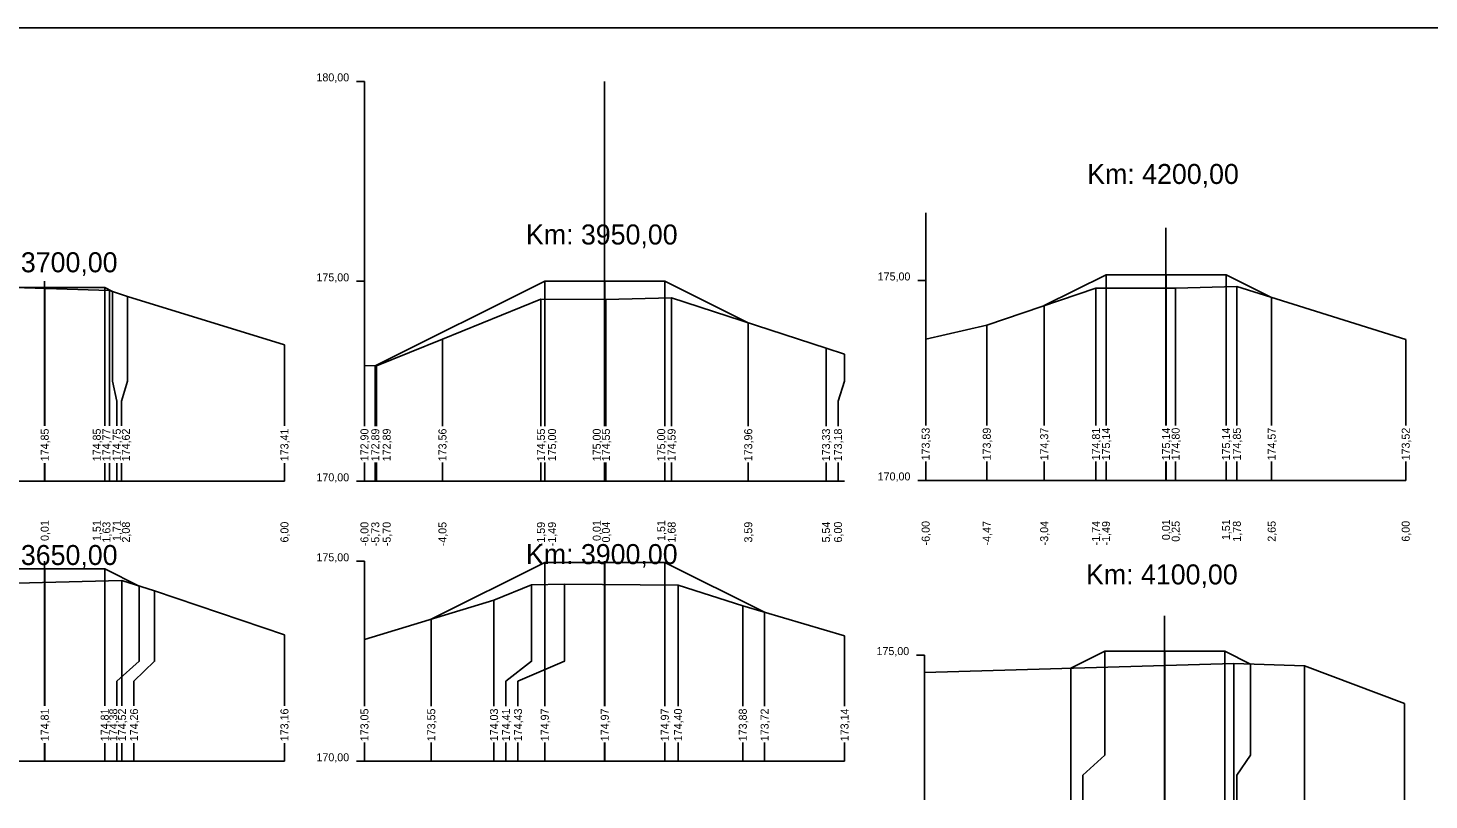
# Model space of a CAD drawing. Extents: x -614174 to -599765, y -1185887 to -1181080.
# Drawn here: x -601012.8 to -600977.78, y -1184510.24 to -1184490.94 of the extents above; entities that cross this region are included whole.
import ezdxf

# ---------------------------------------------------------------- set-up
doc = ezdxf.new("R2010")
doc.units = 0
for name, color, linetype in [('11', 7, 'Continuous'), ('16', 7, 'Continuous'), ('21', 7, 'Continuous'), ('28', 7, 'Continuous'), ('59', 7, 'Continuous'), ('8', 7, 'Continuous'), ('návrh', 7, 'Continuous')]:
    doc.layers.add(name, color=color, linetype=linetype)

msp = doc.modelspace()

# ---------------------------------------------------------------- linework, layer by layer
for points in [[(-600987.397, -1184497.877), (-600985.852, -1184497.104), (-600984.352, -1184497.104), (-600982.852, -1184497.104), (-600981.711, -1184497.675)], [(-600985.852, -1184497.104), (-600985.852, -1184497.104), (-600985.852, -1184497.104)], [(-600984.352, -1184497.104), (-600984.352, -1184497.104), (-600984.352, -1184497.104)], [(-600982.852, -1184497.104), (-600982.852, -1184497.104), (-600982.852, -1184497.104)], [(-601018.389, -1184498.698), (-601014.223, -1184497.525), (-601013.935, -1184497.41), (-601013.687, -1184497.404), (-601010.762, -1184497.497), (-601010.312, -1184497.649), (-601006.389, -1184498.857)], [(-601013.972, -1184497.424), (-601013.881, -1184497.424), (-601012.381, -1184497.424), (-601010.881, -1184497.424), (-601010.683, -1184497.524)], [(-601012.381, -1184497.424), (-601012.381, -1184497.424), (-601012.381, -1184497.424)], [(-601010.881, -1184497.424), (-601010.881, -1184497.424), (-601010.881, -1184497.424)], [(-601004.118, -1184499.383), (-600999.881, -1184497.265), (-600998.381, -1184497.265), (-600996.881, -1184497.265), (-600994.795, -1184498.308)], [(-600999.881, -1184497.265), (-600999.881, -1184497.265), (-600999.881, -1184497.265)], [(-600998.381, -1184497.265), (-600998.381, -1184497.265), (-600998.381, -1184497.265)], [(-600996.881, -1184497.265), (-600996.881, -1184497.265), (-600996.881, -1184497.265)], [(-600990.36, -1184498.72), (-600988.832, -1184498.362), (-600986.104, -1184497.439), (-600984.111, -1184497.444), (-600982.581, -1184497.403), (-600978.36, -1184498.724)], [(-601004.389, -1184499.372), (-601004.091, -1184499.384), (-601002.439, -1184498.714), (-600999.977, -1184497.716), (-600998.353, -1184497.722), (-600996.711, -1184497.682), (-600992.851, -1184498.944), (-600992.389, -1184499.092)], [(-600987.397, -1184497.877), (-600987.397, -1184497.877), (-600987.396, -1184497.877)], [(-601004.118, -1184499.383), (-601004.118, -1184499.383), (-601004.117, -1184499.383)], [(-601015.736, -1184505.384), (-601013.881, -1184504.456), (-601012.381, -1184504.456), (-601010.881, -1184504.456), (-601010.018, -1184504.888)], [(-601012.381, -1184504.456), (-601012.381, -1184504.456), (-601012.381, -1184504.456)], [(-601010.881, -1184504.456), (-601010.881, -1184504.456), (-601010.881, -1184504.456)], [(-601002.719, -1184505.716), (-600999.881, -1184504.297), (-600998.381, -1184504.297), (-600996.881, -1184504.297), (-600994.386, -1184505.545)], [(-600999.881, -1184504.297), (-600999.881, -1184504.297), (-600999.881, -1184504.297)], [(-600998.381, -1184504.297), (-600998.381, -1184504.297), (-600998.381, -1184504.297)], [(-600996.881, -1184504.297), (-600996.881, -1184504.297), (-600996.881, -1184504.297)], [(-601018.389, -1184506.455), (-601014.885, -1184505.04), (-601014.252, -1184504.822), (-601013.765, -1184504.83), (-601010.45, -1184504.75), (-601009.636, -1184505.01), (-601006.389, -1184506.105)], [(-601004.389, -1184506.223), (-601001.151, -1184505.24), (-601000.213, -1184504.862), (-600999.391, -1184504.843), (-600996.55, -1184504.871), (-600994.931, -1184505.385), (-600992.389, -1184506.131)], [(-601002.718, -1184505.715), (-601002.719, -1184505.716), (-601002.719, -1184505.716)], [(-600986.729, -1184506.945), (-600985.881, -1184506.521), (-600984.381, -1184506.521), (-600982.881, -1184506.521), (-600982.24, -1184506.842)], [(-600985.881, -1184506.521), (-600985.881, -1184506.521), (-600985.881, -1184506.521)], [(-600984.381, -1184506.521), (-600984.381, -1184506.521), (-600984.381, -1184506.521)], [(-600982.881, -1184506.521), (-600982.881, -1184506.521), (-600982.881, -1184506.521)], [(-600990.389, -1184507.05), (-600982.655, -1184506.828), (-600980.894, -1184506.885), (-600978.389, -1184507.822)], [(-600986.729, -1184506.945), (-600986.729, -1184506.945), (-600986.729, -1184506.945)]]:
    msp.add_lwpolyline(points)
at = {"layer": '11'}
for points in [[(-600985.852, -1184497.104), (-600985.852, -1184499.748), (-600985.852, -1184500.248), (-600985.852, -1184500.871)], [(-600984.352, -1184497.104), (-600984.352, -1184499.748), (-600984.352, -1184500.248), (-600984.352, -1184500.871)], [(-600982.852, -1184497.104), (-600982.852, -1184499.748), (-600982.852, -1184500.248), (-600982.852, -1184500.871)], [(-601012.381, -1184497.424), (-601012.381, -1184499.77), (-601012.381, -1184500.27), (-601012.381, -1184500.884)], [(-601010.881, -1184497.424), (-601010.881, -1184499.77), (-601010.881, -1184500.27), (-601010.881, -1184500.884)], [(-601010.762, -1184497.497), (-601010.762, -1184499.77), (-601010.762, -1184500.27), (-601010.762, -1184500.884)], [(-601010.683, -1184497.524), (-601010.683, -1184499.77), (-601010.581, -1184500.27), (-601010.581, -1184500.884)], [(-600999.881, -1184497.265), (-600999.881, -1184499.77), (-600999.881, -1184500.27), (-600999.881, -1184500.892)], [(-600998.381, -1184497.265), (-600998.381, -1184499.77), (-600998.381, -1184500.27), (-600998.381, -1184500.892)], [(-600996.881, -1184497.265), (-600996.881, -1184499.77), (-600996.881, -1184500.27), (-600996.881, -1184500.892)], [(-600986.104, -1184497.439), (-600986.104, -1184499.748), (-600986.104, -1184500.248), (-600986.104, -1184500.871)], [(-600984.111, -1184497.444), (-600984.111, -1184499.748), (-600984.111, -1184500.248), (-600984.111, -1184500.871)], [(-600982.581, -1184497.403), (-600982.581, -1184499.748), (-600982.581, -1184500.248), (-600982.581, -1184500.871)], [(-601010.312, -1184497.649), (-601010.312, -1184499.77), (-601010.462, -1184500.27), (-601010.462, -1184500.884)], [(-600999.977, -1184497.716), (-600999.977, -1184499.77), (-600999.977, -1184500.27), (-600999.977, -1184500.892)], [(-600998.353, -1184497.722), (-600998.353, -1184499.77), (-600998.353, -1184500.27), (-600998.353, -1184500.892)], [(-600996.711, -1184497.682), (-600996.711, -1184499.77), (-600996.711, -1184500.27), (-600996.711, -1184500.892)], [(-600987.397, -1184497.877), (-600987.397, -1184499.748), (-600987.397, -1184500.248), (-600987.397, -1184500.871)], [(-600981.711, -1184497.675), (-600981.711, -1184499.748), (-600981.711, -1184500.248), (-600981.711, -1184500.871)], [(-600994.795, -1184498.308), (-600994.795, -1184499.77), (-600994.795, -1184500.27), (-600994.795, -1184500.892)], [(-600988.832, -1184498.362), (-600988.832, -1184499.748), (-600988.832, -1184500.248), (-600988.832, -1184500.871)], [(-601006.389, -1184498.857), (-601006.389, -1184499.77), (-601006.389, -1184500.27), (-601006.389, -1184500.884)], [(-601002.439, -1184498.714), (-601002.439, -1184499.77), (-601002.439, -1184500.27), (-601002.439, -1184500.892)], [(-600992.851, -1184498.944), (-600992.851, -1184499.77), (-600992.851, -1184500.27), (-600992.851, -1184500.892)], [(-600990.36, -1184498.72), (-600990.36, -1184499.748), (-600990.36, -1184500.248), (-600990.36, -1184500.871)], [(-600978.36, -1184498.724), (-600978.36, -1184499.748), (-600978.36, -1184500.248), (-600978.36, -1184500.871)], [(-600992.389, -1184499.092), (-600992.389, -1184499.77), (-600992.551, -1184500.27), (-600992.551, -1184500.892)], [(-601004.389, -1184499.372), (-601004.389, -1184499.77), (-601004.389, -1184500.27), (-601004.389, -1184500.892)], [(-601004.118, -1184499.383), (-601004.118, -1184499.77), (-601004.118, -1184500.27), (-601004.118, -1184500.892)], [(-601004.091, -1184499.384), (-601004.091, -1184499.77), (-601004.089, -1184500.27), (-601004.089, -1184500.892)], [(-601012.381, -1184501.82), (-601012.381, -1184502.27)], [(-601010.881, -1184501.82), (-601010.881, -1184502.27)], [(-601010.762, -1184501.82), (-601010.762, -1184502.27)], [(-601010.581, -1184501.82), (-601010.581, -1184502.27)], [(-601010.462, -1184501.82), (-601010.462, -1184502.27)], [(-601006.389, -1184501.82), (-601006.389, -1184502.27)], [(-601004.389, -1184501.8), (-601004.389, -1184502.27)], [(-601004.118, -1184501.8), (-601004.118, -1184502.27)], [(-601004.089, -1184501.8), (-601004.089, -1184502.27)], [(-601002.439, -1184501.8), (-601002.439, -1184502.27)], [(-600999.977, -1184501.8), (-600999.977, -1184502.27)], [(-600999.881, -1184501.8), (-600999.881, -1184502.27)], [(-600998.381, -1184501.8), (-600998.381, -1184502.27)], [(-600998.353, -1184501.8), (-600998.353, -1184502.27)], [(-600996.881, -1184501.8), (-600996.881, -1184502.27)], [(-600996.711, -1184501.8), (-600996.711, -1184502.27)], [(-600994.795, -1184501.8), (-600994.795, -1184502.27)], [(-600992.851, -1184501.8), (-600992.851, -1184502.27)], [(-600992.551, -1184501.8), (-600992.551, -1184502.27)], [(-600990.36, -1184501.779), (-600990.36, -1184502.248)], [(-600988.832, -1184501.779), (-600988.832, -1184502.248)], [(-600987.397, -1184501.779), (-600987.397, -1184502.248)], [(-600986.104, -1184501.779), (-600986.104, -1184502.248)], [(-600985.852, -1184501.779), (-600985.852, -1184502.248)], [(-600984.352, -1184501.779), (-600984.352, -1184502.248)], [(-600984.111, -1184501.779), (-600984.111, -1184502.248)], [(-600982.852, -1184501.779), (-600982.852, -1184502.248)], [(-600982.581, -1184501.779), (-600982.581, -1184502.248)], [(-600981.711, -1184501.779), (-600981.711, -1184502.248)], [(-600978.36, -1184501.779), (-600978.36, -1184502.248)], [(-601012.381, -1184504.456), (-601012.381, -1184506.77), (-601012.381, -1184507.27), (-601012.381, -1184507.884)], [(-601010.881, -1184504.456), (-601010.881, -1184506.77), (-601010.881, -1184507.27), (-601010.881, -1184507.884)], [(-600999.881, -1184504.297), (-600999.881, -1184506.77), (-600999.881, -1184507.27), (-600999.881, -1184507.892)], [(-600998.381, -1184504.297), (-600998.381, -1184506.77), (-600998.381, -1184507.27), (-600998.381, -1184507.892)], [(-600996.881, -1184504.297), (-600996.881, -1184506.77), (-600996.881, -1184507.27), (-600996.881, -1184507.892)], [(-601010.018, -1184504.888), (-601010.018, -1184506.77), (-601010.581, -1184507.27), (-601010.581, -1184507.884)], [(-601010.45, -1184504.75), (-601010.45, -1184506.77), (-601010.45, -1184507.27), (-601010.45, -1184507.884)], [(-601000.213, -1184504.862), (-601000.213, -1184506.77), (-601000.851, -1184507.27), (-601000.851, -1184507.892)], [(-600999.391, -1184504.843), (-600999.391, -1184506.77), (-601000.551, -1184507.27), (-601000.551, -1184507.892)], [(-600996.55, -1184504.871), (-600996.55, -1184506.77), (-600996.55, -1184507.27), (-600996.55, -1184507.892)], [(-601009.636, -1184505.01), (-601009.636, -1184506.77), (-601010.15, -1184507.27), (-601010.15, -1184507.884)], [(-601001.151, -1184505.24), (-601001.151, -1184506.77), (-601001.151, -1184507.27), (-601001.151, -1184507.892)], [(-600994.931, -1184505.385), (-600994.931, -1184506.77), (-600994.931, -1184507.27), (-600994.931, -1184507.892)], [(-600994.386, -1184505.545), (-600994.386, -1184506.77), (-600994.386, -1184507.27), (-600994.386, -1184507.892)], [(-601002.719, -1184505.716), (-601002.719, -1184506.77), (-601002.719, -1184507.27), (-601002.719, -1184507.892)], [(-601006.389, -1184506.105), (-601006.389, -1184506.77), (-601006.389, -1184507.27), (-601006.389, -1184507.884)], [(-601004.389, -1184506.223), (-601004.389, -1184506.77), (-601004.389, -1184507.27), (-601004.389, -1184507.892)], [(-600992.389, -1184506.131), (-600992.389, -1184506.77), (-600992.389, -1184507.27), (-600992.389, -1184507.892)], [(-600985.881, -1184506.521), (-600985.881, -1184509.115), (-600986.429, -1184509.615), (-600986.429, -1184510.238)], [(-600984.381, -1184506.521), (-600984.381, -1184509.115), (-600984.381, -1184509.615), (-600984.381, -1184510.238)], [(-600982.881, -1184506.521), (-600982.881, -1184509.115), (-600982.881, -1184509.615), (-600982.881, -1184510.238)], [(-600986.729, -1184506.945), (-600986.729, -1184509.115), (-600986.729, -1184509.615), (-600986.729, -1184510.238)], [(-600982.655, -1184506.828), (-600982.655, -1184509.115), (-600982.655, -1184509.615), (-600982.655, -1184510.238)], [(-600982.24, -1184506.842), (-600982.24, -1184509.115), (-600982.581, -1184509.615), (-600982.581, -1184510.238)], [(-600980.894, -1184506.885), (-600980.894, -1184509.115), (-600980.894, -1184509.615), (-600980.894, -1184510.238)], [(-600990.389, -1184507.05), (-600990.389, -1184509.115), (-600990.389, -1184509.615), (-600990.389, -1184510.238)], [(-600978.389, -1184507.822), (-600978.389, -1184509.115), (-600978.389, -1184509.615), (-600978.389, -1184510.238)], [(-601012.381, -1184508.82), (-601012.381, -1184509.27)], [(-601010.881, -1184508.82), (-601010.881, -1184509.27)], [(-601010.581, -1184508.82), (-601010.581, -1184509.27)], [(-601010.45, -1184508.82), (-601010.45, -1184509.27)], [(-601010.15, -1184508.82), (-601010.15, -1184509.27)], [(-601006.389, -1184508.82), (-601006.389, -1184509.27)], [(-601004.389, -1184508.8), (-601004.389, -1184509.27)], [(-601002.719, -1184508.8), (-601002.719, -1184509.27)], [(-601001.151, -1184508.8), (-601001.151, -1184509.27)], [(-601000.851, -1184508.8), (-601000.851, -1184509.27)], [(-601000.551, -1184508.8), (-601000.551, -1184509.27)], [(-600999.881, -1184508.8), (-600999.881, -1184509.27)], [(-600998.381, -1184508.8), (-600998.381, -1184509.27)], [(-600996.881, -1184508.8), (-600996.881, -1184509.27)], [(-600996.55, -1184508.8), (-600996.55, -1184509.27)], [(-600994.931, -1184508.8), (-600994.931, -1184509.27)], [(-600994.386, -1184508.8), (-600994.386, -1184509.27)], [(-600992.389, -1184508.8), (-600992.389, -1184509.27)]]:
    msp.add_lwpolyline(points, dxfattribs=at)
at = {"layer": '16'}
for p, q in [((-601018.389, -1184502.27), (-601006.389, -1184502.27)), ((-601004.389, -1184502.27), (-600992.389, -1184502.27)), ((-600990.36, -1184502.248), (-600978.36, -1184502.248)), ((-601018.389, -1184509.27), (-601006.389, -1184509.27)), ((-601004.389, -1184509.27), (-600992.389, -1184509.27))]:
    msp.add_line(p, q, dxfattribs=at)
for points in [[(-601010.683, -1184497.524), (-601010.683, -1184497.524), (-601010.683, -1184497.523)], [(-600981.711, -1184497.675), (-600981.711, -1184497.675), (-600981.711, -1184497.675)], [(-600994.795, -1184498.309), (-600994.795, -1184498.308), (-600994.795, -1184498.308)], [(-601010.019, -1184504.888), (-601010.018, -1184504.888), (-601010.018, -1184504.888)], [(-600994.386, -1184505.545), (-600994.386, -1184505.545), (-600994.386, -1184505.545)], [(-600982.24, -1184506.842), (-600982.24, -1184506.842), (-600982.24, -1184506.842)]]:
    msp.add_lwpolyline(points, dxfattribs=at)
at = {"layer": '21'}
for p, q in [((-601004.589, -1184492.27), (-601004.389, -1184492.27)), ((-601004.589, -1184497.27), (-601004.389, -1184497.27)), ((-600990.56, -1184497.248), (-600990.36, -1184497.248)), ((-601004.589, -1184502.27), (-601004.389, -1184502.27)), ((-600990.56, -1184502.248), (-600990.36, -1184502.248)), ((-601004.589, -1184504.27), (-601004.389, -1184504.27)), ((-600990.589, -1184506.615), (-600990.389, -1184506.615)), ((-601004.589, -1184509.27), (-601004.389, -1184509.27))]:
    msp.add_line(p, q, dxfattribs=at)
at = {"layer": '28'}
for p, q in [((-600998.389, -1184500.892), (-600998.389, -1184492.27)), ((-600984.36, -1184500.871), (-600984.36, -1184495.933)), ((-601012.389, -1184500.884), (-601012.389, -1184497.27)), ((-601012.389, -1184502.27), (-601012.389, -1184501.82)), ((-600998.389, -1184502.27), (-600998.389, -1184501.8)), ((-600984.36, -1184502.248), (-600984.36, -1184501.779)), ((-601012.389, -1184507.884), (-601012.389, -1184504.27)), ((-600998.389, -1184507.892), (-600998.389, -1184504.27)), ((-600984.389, -1184510.238), (-600984.389, -1184505.631)), ((-601012.389, -1184509.27), (-601012.389, -1184508.82)), ((-600998.389, -1184509.27), (-600998.389, -1184508.8))]:
    msp.add_line(p, q, dxfattribs=at)
at = {"layer": '8'}
for p, q in [((-601004.389, -1184500.892), (-601004.389, -1184492.27)), ((-600990.36, -1184500.871), (-600990.36, -1184495.555)), ((-601004.389, -1184502.27), (-601004.389, -1184501.8)), ((-600990.36, -1184502.248), (-600990.36, -1184501.779)), ((-601004.389, -1184507.892), (-601004.389, -1184504.27)), ((-600990.389, -1184510.238), (-600990.389, -1184506.615)), ((-601004.389, -1184509.27), (-601004.389, -1184508.8))]:
    msp.add_line(p, q, dxfattribs=at)
at = {"layer": 'návrh'}
msp.add_line((-601090.944, -1184490.936), (-600943.944, -1184490.936), dxfattribs=at)

# ---------------------------------------------------------------- texts
at = {"layer": '16'}
for s, p in [('174,85', (-601012.281, -1184501.77)), ('174,85', (-601010.98, -1184501.77)), ('174,77', (-601010.739, -1184501.77)), ('174,75', (-601010.481, -1184501.77)), ('174,62', (-601010.253, -1184501.77)), ('173,41', (-601006.289, -1184501.77)), ('172,90', (-601004.289, -1184501.77)), ('172,89', (-601004.018, -1184501.77)), ('172,89', (-601003.733, -1184501.77)), ('173,56', (-601002.339, -1184501.77)), ('174,55', (-600999.877, -1184501.77)), ('175,00', (-600999.601, -1184501.77)), ('175,00', (-600998.482, -1184501.77)), ('174,55', (-600998.253, -1184501.77)), ('175,00', (-600996.871, -1184501.77)), ('174,59', (-600996.611, -1184501.77)), ('173,96', (-600994.695, -1184501.77)), ('173,33', (-600992.751, -1184501.77)), ('173,18', (-600992.451, -1184501.77)), ('173,53', (-600990.26, -1184501.748)), ('173,89', (-600988.732, -1184501.748)), ('174,37', (-600987.297, -1184501.748)), ('174,81', (-600986.004, -1184501.748)), ('175,14', (-600985.752, -1184501.748)), ('175,14', (-600984.252, -1184501.748)), ('174,80', (-600984.011, -1184501.748)), ('175,14', (-600982.752, -1184501.748)), ('174,85', (-600982.481, -1184501.748)), ('174,57', (-600981.611, -1184501.748)), ('173,52', (-600978.26, -1184501.748)), ('174,81', (-601012.281, -1184508.77)), ('174,81', (-601010.781, -1184508.77)), ('174,38', (-601010.568, -1184508.77)), ('174,52', (-601010.35, -1184508.77)), ('174,26', (-601010.05, -1184508.77)), ('173,16', (-601006.289, -1184508.77)), ('173,05', (-601004.289, -1184508.77)), ('173,55', (-601002.619, -1184508.77)), ('174,03', (-601001.051, -1184508.77)), ('174,41', (-601000.751, -1184508.77)), ('174,43', (-601000.451, -1184508.77)), ('174,97', (-600999.781, -1184508.77)), ('174,97', (-600998.281, -1184508.77)), ('174,97', (-600996.781, -1184508.77)), ('174,40', (-600996.45, -1184508.77)), ('173,88', (-600994.831, -1184508.77)), ('173,72', (-600994.286, -1184508.77)), ('173,14', (-600992.289, -1184508.77))]:
    msp.add_text(s, height=0.2, rotation=90, dxfattribs=at).set_placement(p)
at = {"layer": '21'}
for s, p in [('180,00', (-601005.589, -1184492.27)), ('175,00', (-601005.589, -1184497.27)), ('175,00', (-600991.56, -1184497.248)), ('170,00', (-601005.589, -1184502.27)), ('170,00', (-600991.56, -1184502.248)), ('175,00', (-601005.589, -1184504.27)), ('175,00', (-600991.589, -1184506.615)), ('170,00', (-601005.589, -1184509.27))]:
    msp.add_text(s, height=0.2, dxfattribs=at).set_placement(p)
at = {"layer": '28'}
for s, p in [('Km: 4200,00', (-600986.323, -1184494.836)), ('Km: 3950,00', (-601000.352, -1184496.349)), ('Km: 3700,00', (-601014.352, -1184497.044)), ('Km: 3650,00', (-601014.352, -1184504.363)), ('Km: 3900,00', (-601000.352, -1184504.34)), ('Km: 4100,00', (-600986.352, -1184504.848))]:
    msp.add_text(s, height=0.5, dxfattribs=at).set_placement(p)
at = {"layer": '59'}
for s, p in [('0,01', (-601012.281, -1184503.762)), ('1,51', (-601010.98, -1184503.762)), ('1,63', (-601010.739, -1184503.801)), ('1,71', (-601010.481, -1184503.762)), ('2,08', (-601010.253, -1184503.801)), ('6,00', (-601006.289, -1184503.8)), ('-6,00', (-601004.289, -1184503.893)), ('-5,73', (-601004.018, -1184503.894)), ('-5,70', (-601003.733, -1184503.893)), ('-4,05', (-601002.339, -1184503.895)), ('-1,59', (-600999.877, -1184503.894)), ('-1,49', (-600999.601, -1184503.894)), ('0,01', (-600998.482, -1184503.762)), ('0,04', (-600998.253, -1184503.8)), ('1,51', (-600996.871, -1184503.762)), ('1,68', (-600996.611, -1184503.801)), ('3,59', (-600994.695, -1184503.801)), ('5,54', (-600992.751, -1184503.8)), ('6,00', (-600992.451, -1184503.8)), ('-6,00', (-600990.26, -1184503.872)), ('-4,47', (-600988.732, -1184503.872)), ('-3,04', (-600987.297, -1184503.871)), ('-1,74', (-600986.004, -1184503.871)), ('-1,49', (-600985.752, -1184503.873)), ('0,01', (-600984.252, -1184503.741)), ('0,25', (-600984.011, -1184503.781)), ('1,51', (-600982.752, -1184503.741)), ('1,78', (-600982.481, -1184503.78)), ('2,65', (-600981.611, -1184503.781)), ('6,00', (-600978.26, -1184503.779))]:
    msp.add_text(s, height=0.2, rotation=90, dxfattribs=at).set_placement(p)

doc.saveas('drawing.dxf')
